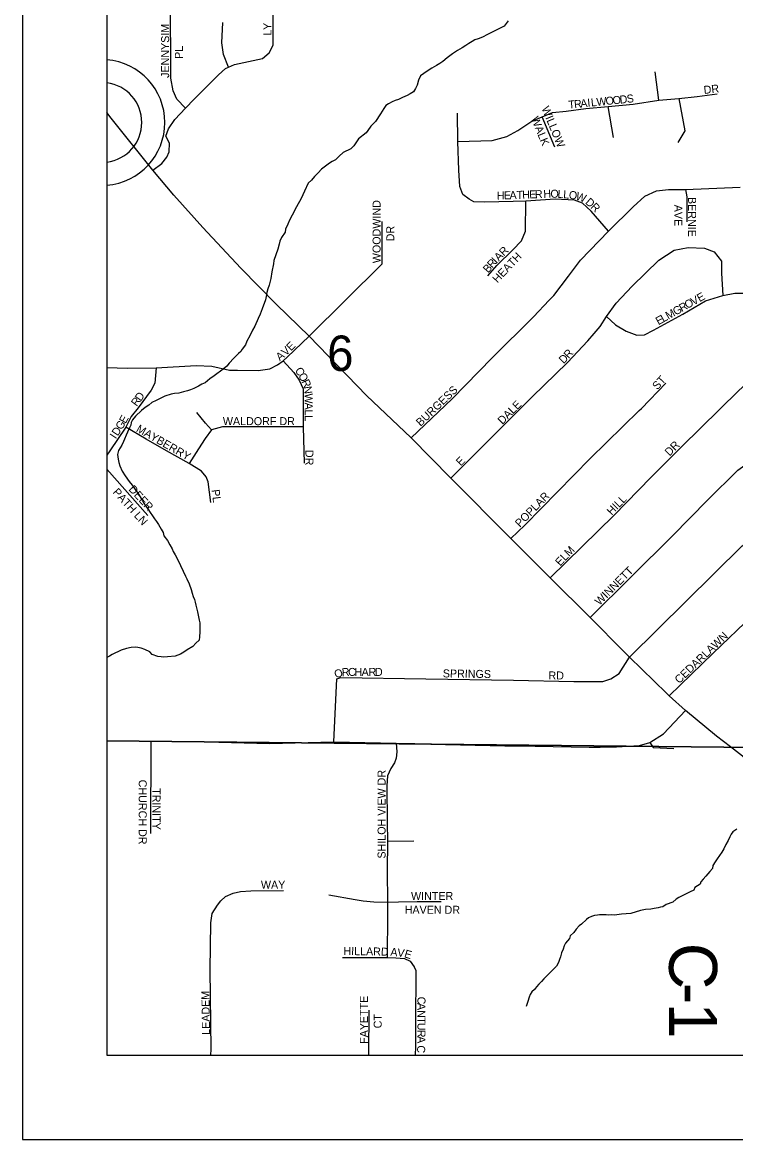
# Model space of a CAD drawing. Extents: x 8.5 to 81.5, y -1.2 to 22.4.
# Drawn here: x 49.353 to 50.196, y 14.351 to 15.672 of the extents above; entities that cross this region are included whole.
import ezdxf

# ---------------------------------------------------------------- set-up
doc = ezdxf.new("R2010")
doc.units = 0
for name, color, linetype in [('GM_X_County', 7, 'Continuous'), ('GM_X_County_Road', 7, 'Continuous'), ('GM_X_County_Road_Text', 7, 'Continuous'), ('GM_X_Minor_River', 7, 'Continuous'), ('GM_X_Section', 7, 'Continuous'), ('GM_X_Section_Text', 7, 'Continuous'), ('GM_X_State_Route', 7, 'Continuous'), ('GM_X_Township', 7, 'Continuous'), ('GM_X_Township_Road', 7, 'Continuous'), ('GM_X_Township_Subdivision', 7, 'Continuous'), ('GM_X_Township_Subdivision_Text', 7, 'Continuous'), ('GM_X_Unincorporated', 7, 'Continuous'), ('SH_Data', 7, 'Continuous')]:
    doc.layers.add(name, color=color, linetype=linetype)

msp = doc.modelspace()

# ---------------------------------------------------------------- linework, layer by layer
at = {"layer": 'GM_X_County'}
msp.add_lwpolyline([(54.0879, 21.2506), (49.4527, 21.2506), (49.4527, 14.4506), (56.2527, 14.4506), (56.2527, 19.1108)], dxfattribs=at)
at = {"layer": 'GM_X_County_Road'}
msp.add_lwpolyline([(49.4527, 14.8224), (49.5047, 14.8219), (49.5551, 14.8213), (49.6451, 14.819), (49.721, 14.821), (49.7946, 14.8196), (49.8168, 14.8191), (49.8359, 14.8182), (49.9231, 14.8164), (49.9377, 14.8162), (50.0228, 14.8149), (50.0359, 14.8149), (50.0554, 14.8152), (50.0823, 14.8169), (50.0945, 14.8203), (50.1107, 14.8305), (50.1369, 14.8581)], dxfattribs=at)
at = {"layer": 'GM_X_Minor_River'}
for points in [[(49.927, 15.6737), (49.9223, 15.6677), (49.9139, 15.6633), (49.9089, 15.6607), (49.9027, 15.6578), (49.8966, 15.6545), (49.8916, 15.6527), (49.8878, 15.6513), (49.8844, 15.6494), (49.8805, 15.6472), (49.877, 15.6446), (49.8728, 15.642), (49.8674, 15.6387), (49.8613, 15.6347), (49.8551, 15.6302), (49.8497, 15.6258), (49.8462, 15.6232), (49.8424, 15.621), (49.837, 15.6177), (49.8324, 15.6151), (49.8274, 15.6114), (49.8236, 15.6088), (49.8212, 15.6035), (49.8195, 15.5979), (49.8176, 15.5937), (49.8152, 15.59), (49.8114, 15.5874), (49.8079, 15.5855), (49.8022, 15.583), (49.7976, 15.5808), (49.7934, 15.5794), (49.7899, 15.5779), (49.7857, 15.5757), (49.7826, 15.5735), (49.7803, 15.5701), (49.776, 15.5638), (49.7701, 15.5547), (49.7647, 15.5491), (49.7611, 15.5443), (49.7592, 15.5413), (49.7503, 15.5342), (49.7448, 15.526), (49.741, 15.5226), (49.7321, 15.5179), (49.7275, 15.5138), (49.7229, 15.5093), (49.719, 15.5075)], [(49.719, 15.5075), (49.716, 15.5056), (49.7063, 15.4982), (49.7024, 15.4941), (49.6982, 15.4896), (49.6947, 15.4855), (49.6908, 15.4818), (49.6864, 15.4724), (49.6825, 15.4637), (49.6769, 15.4539), (49.6718, 15.4441), (49.6687, 15.4381), (49.6667, 15.4332), (49.6639, 15.4276), (49.6634, 15.4238), (49.6591, 15.4174), (49.6571, 15.4133), (49.6563, 15.4098), (49.6547, 15.4038), (49.6526, 15.397), (49.6502, 15.3902), (49.6498, 15.3864), (49.6477, 15.3769), (49.6464, 15.369), (49.6447, 15.361), (49.6431, 15.3569), (49.6418, 15.3527), (49.641, 15.3478), (49.6401, 15.344), (49.6361, 15.333), (49.6341, 15.327), (49.6317, 15.3217), (49.6277, 15.3127), (49.625, 15.3078), (49.6218, 15.3014), (49.6183, 15.295), (49.6167, 15.2908), (49.6128, 15.2856), (49.6112, 15.2826), (49.6081, 15.2804), (49.6027, 15.2748), (49.5972, 15.2688), (49.5945, 15.2654), (49.5903, 15.2617), (49.5795, 15.2539), (49.5745, 15.2502), (49.5687, 15.2458), (49.5649, 15.2439), (49.561, 15.2417), (49.5553, 15.2388), (49.5514, 15.2374), (49.548, 15.2363), (49.5434, 15.2349), (49.5377, 15.2335), (49.5328, 15.2332), (49.5286, 15.2321), (49.5213, 15.23), (49.5179, 15.2285), (49.5148, 15.2267), (49.511, 15.2249), (49.506, 15.2223), (49.5021, 15.2193), (49.4979, 15.2164), (49.4936, 15.213), (49.4867, 15.2063), (49.4828, 15.2018), (49.4812, 15.1988), (49.4808, 15.1954), (49.4795, 15.1924), (49.4772, 15.1875), (49.4756, 15.1837), (49.4736, 15.1792), (49.4724, 15.1762), (49.4704, 15.172), (49.4684, 15.1686), (49.4665, 15.1656), (49.4652, 15.1611), (49.4659, 15.1554), (49.4669, 15.1516), (49.468, 15.1474), (49.4709, 15.1412), (49.4742, 15.1358), (49.479, 15.1289), (49.4827, 15.1246), (49.486, 15.1196), (49.4893, 15.115), (49.4919, 15.1107), (49.4945, 15.1069), (49.4963, 15.1034), (49.4985, 15.1003), (49.5011, 15.0965), (49.5037, 15.0922), (49.5066, 15.0884), (49.5088, 15.0849), (49.5114, 15.0818), (49.5136, 15.078), (49.5169, 15.0726), (49.5191, 15.0687), (49.5202, 15.0649), (49.5242, 15.0591), (49.5272, 15.0541)], [(49.5272, 15.0541), (49.5297, 15.0495), (49.5312, 15.046), (49.5334, 15.0422), (49.537, 15.0356), (49.5457, 15.0172), (49.5472, 15.0138), (49.5501, 15.008), (49.5522, 15.0011), (49.5537, 14.9969), (49.5547, 14.9931), (49.5562, 14.9896), (49.5569, 14.9862), (49.5579, 14.9827), (49.559, 14.9778), (49.5597, 14.9747), (49.5611, 14.969), (49.5617, 14.9651), (49.5624, 14.9617), (49.5626, 14.951), (49.5621, 14.9453), (49.5616, 14.9415), (49.5578, 14.9378), (49.5543, 14.9337), (49.5474, 14.9297), (49.5435, 14.9271), (49.5397, 14.9249), (49.5366, 14.9234), (49.5335, 14.9223), (49.5244, 14.9217), (49.5202, 14.9214), (49.5168, 14.9215), (49.513, 14.922), (49.5063, 14.9244), (49.5033, 14.9275), (49.4977, 14.9303), (49.4931, 14.9319), (49.4894, 14.9327), (49.486, 14.9332), (49.4814, 14.9325), (49.4757, 14.9315), (49.4696, 14.9293), (49.4588, 14.9242), (49.4558, 14.9223), (49.4527, 14.9209)], [(50.1975, 14.7176), (50.1929, 14.7147), (50.1909, 14.7117), (50.1893, 14.7086), (50.1874, 14.7045), (50.1846, 14.6996), (50.1822, 14.6947), (50.1799, 14.6906), (50.1744, 14.6827), (50.172, 14.6793), (50.1693, 14.6748), (50.1688, 14.6714), (50.1657, 14.6676), (50.1607, 14.662), (50.1579, 14.6586), (50.1548, 14.6553), (50.154, 14.6526), (50.1479, 14.6486), (50.1467, 14.6455), (50.1425, 14.6437), (50.1382, 14.6415), (50.1329, 14.639), (50.129, 14.6368), (50.1256, 14.6349), (50.1217, 14.6316), (50.1141, 14.6287), (50.1102, 14.6261), (50.1072, 14.6254), (50.1045, 14.6247), (50.0996, 14.624), (50.0957, 14.6233), (50.0897, 14.6227), (50.0836, 14.6217), (50.0721, 14.6181), (50.0611, 14.6172), (50.0558, 14.6165), (50.0523, 14.6162), (50.0489, 14.6163), (50.0463, 14.616), (50.0429, 14.6164)], [(50.0429, 14.6164), (50.0353, 14.6166), (50.0326, 14.6162), (50.0292, 14.6155), (50.0257, 14.6145), (50.0223, 14.613), (50.0196, 14.6108), (50.0138, 14.6056), (50.0111, 14.6033), (50.0076, 14.5996), (50.0049, 14.5955), (50.0006, 14.5917), (49.9998, 14.5883), (49.9951, 14.5831), (49.9935, 14.5797), (49.9923, 14.5759), (49.9903, 14.5714), (49.9891, 14.5668), (49.9879, 14.5638), (49.9867, 14.56), (49.9843, 14.5559), (49.9781, 14.5495), (49.9715, 14.5432), (49.9692, 14.5406), (49.9665, 14.5376), (49.9634, 14.5346), (49.9606, 14.5312), (49.9583, 14.5282), (49.9552, 14.5253), (49.9533, 14.5222), (49.9521, 14.5192), (49.9504, 14.5139), (49.9492, 14.5105), (49.9484, 14.5079)]]:
    msp.add_lwpolyline(points, dxfattribs=at)
at = {"layer": 'GM_X_Section'}
msp.add_line((49.4527, 15.7683), (49.4527, 14.8223), dxfattribs=at)
for points in [[(49.4527, 14.8223), (50.2203, 14.8143), (50.2298, 15.7659), (49.4527, 15.7683)], [(49.4527, 14.8223), (49.4527, 14.4506), (50.2199, 14.4506)], [(50.2199, 14.4506), (50.219, 14.7462), (50.2203, 14.8143), (49.4527, 14.8223)]]:
    msp.add_lwpolyline(points, dxfattribs=at)
at = {"layer": 'GM_X_State_Route'}
for points in [[(49.9326, 15.059), (49.9303, 15.0614), (49.8595, 15.1329), (49.8123, 15.1806), (49.7598, 15.2308), (49.6917, 15.301), (49.6534, 15.3385), (49.611, 15.3814), (49.5661, 15.4295), (49.5317, 15.4678), (49.507, 15.497), (49.4579, 15.5586), (49.4527, 15.5653)], [(50.0641, 14.928), (50.0242, 14.968), (49.9768, 15.0149), (49.9326, 15.059)], [(50.1144, 14.8787), (50.0707, 14.9213), (50.0641, 14.928)], [(50.1899, 14.8152), (50.1734, 14.8279), (50.1369, 14.8581), (50.1177, 14.8754), (50.1144, 14.8787)], [(50.5585, 14.4506), (50.5576, 14.4519), (50.5438, 14.4699), (50.524, 14.4914), (50.4321, 14.5898), (50.4041, 14.6199), (50.3659, 14.6612), (50.3179, 14.7117), (50.2995, 14.7293), (50.2169, 14.7944), (50.1899, 14.8152)]]:
    msp.add_lwpolyline(points, dxfattribs=at)
at = {"layer": 'GM_X_Township'}
msp.add_lwpolyline([(49.4527, 15.7601), (49.4527, 14.4506), (54.4602, 14.4506)], dxfattribs=at)
at = {"layer": 'GM_X_Township_Road'}
msp.add_lwpolyline([(50.0945, 14.8203), (50.0984, 14.8145), (50.1231, 14.8133)], dxfattribs=at)
at = {"layer": 'GM_X_Township_Subdivision'}
for points in [[(49.5458, 15.5704), (49.5355, 15.581), (49.5309, 15.5909), (49.5282, 15.6062), (49.5282, 15.6412), (49.5276, 15.6942), (49.5289, 15.7081), (49.5329, 15.7193)], [(49.507, 15.497), (49.5177, 15.5052), (49.5234, 15.5124), (49.5262, 15.5189), (49.5268, 15.5293), (49.5223, 15.5373), (49.5256, 15.5459), (49.5329, 15.5572), (49.5458, 15.5704), (49.556, 15.581), (49.5845, 15.6101), (49.5931, 15.6174), (49.5965, 15.6189), (49.6037, 15.622), (49.6368, 15.6293), (49.6447, 15.6359), (49.6493, 15.6452), (49.6493, 15.6677), (49.6487, 15.7034)], [(49.5965, 15.6189), (49.5905, 15.6339), (49.5885, 15.6479), (49.5898, 15.6717)], [(50.1052, 15.5801), (50.1011, 15.6134)], [(49.8678, 15.5312), (49.9083, 15.5323), (49.9257, 15.5372), (49.9386, 15.5442), (49.9553, 15.5553), (49.9675, 15.5601), (49.9797, 15.5653), (49.9956, 15.5668), (50.019, 15.5701), (50.0452, 15.5723), (50.0748, 15.5753), (50.1052, 15.5801), (50.1289, 15.5818), (50.1507, 15.5845), (50.1741, 15.5875)], [(50.1289, 15.5818), (50.1362, 15.5437), (50.1279, 15.5299)], [(50.0515, 15.536), (50.0452, 15.5723)], [(50.0458, 15.425), (50.0252, 15.4487), (50.0152, 15.4583), (50.0056, 15.4616), (49.9827, 15.4627), (49.9482, 15.4605), (49.9331, 15.4602), (49.899, 15.4594), (49.8864, 15.4598), (49.8809, 15.4627), (49.8734, 15.4686), (49.8698, 15.4777), (49.8689, 15.497), (49.8678, 15.5312), (49.8672, 15.5646)], [(49.9824, 15.5244), (49.9675, 15.5601)], [(49.9756, 15.3433), (49.9812, 15.3491), (49.9986, 15.372), (50.0127, 15.3909), (50.0458, 15.425), (50.0748, 15.4539), (50.0889, 15.4664), (50.1026, 15.4727), (50.1167, 15.4742), (50.137, 15.4742), (50.2015, 15.4772)], [(50.137, 15.4742), (50.1382, 15.4657), (50.1385, 15.4361)], [(49.9031, 15.3724), (49.9138, 15.3846), (49.9327, 15.4031), (49.9431, 15.4135), (49.9475, 15.425), (49.9482, 15.4605)], [(49.7782, 15.3865), (49.7782, 15.4365)], [(50.0287, 15.304), (50.0358, 15.3122), (50.0433, 15.3241), (50.0549, 15.3399), (50.0738, 15.36), (50.1052, 15.3908), (50.1236, 15.4025), (50.14, 15.4058), (50.1594, 15.405), (50.1708, 15.4005), (50.1795, 15.3896), (50.1794, 15.3755), (50.1808, 15.3491)], [(49.6917, 15.301), (49.7782, 15.3865)], [(49.8123, 15.1806), (49.8611, 15.2268), (49.9083, 15.2753), (49.9571, 15.3239), (49.9756, 15.3433)], [(50.0433, 15.3241), (50.0541, 15.3144), (50.0666, 15.3066), (50.0791, 15.3022), (50.0883, 15.3024), (50.0988, 15.308), (50.1336, 15.3269), (50.1605, 15.3427), (50.1808, 15.3491), (50.195, 15.3516), (50.2089, 15.3519), (50.2228, 15.3516), (50.2425, 15.3505), (50.2623, 15.3494), (50.2767, 15.341), (50.2851, 15.334), (50.2901, 15.3241), (50.2906, 15.3122), (50.2898, 15.2876)], [(49.8595, 15.1329), (49.9113, 15.185), (49.9556, 15.2291), (49.9974, 15.2696), (50.0213, 15.2955), (50.0287, 15.304)], [(49.6072, 15.2606), (49.6317, 15.2603), (49.6453, 15.2622), (49.6544, 15.2668), (49.6611, 15.2718), (49.6659, 15.2759), (49.6917, 15.301)], [(49.9768, 15.0149), (50.0523, 15.089), (50.0959, 15.1337), (50.1326, 15.1704), (50.1995, 15.2363), (50.2138, 15.2494), (50.2374, 15.2728), (50.2475, 15.2815), (50.2564, 15.2867), (50.2898, 15.2876), (50.3267, 15.286), (50.3534, 15.2866), (50.3868, 15.2844), (50.416, 15.2821), (50.4751, 15.2804)], [(49.4527, 15.2637), (49.477, 15.2632), (49.511, 15.2635), (49.5581, 15.2663), (49.5768, 15.2654), (49.5975, 15.2607), (49.6072, 15.2606)], [(49.511, 15.2635), (49.5093, 15.2453), (49.5052, 15.2371), (49.4895, 15.2161), (49.4813, 15.2057), (49.475, 15.1934), (49.4562, 15.1653), (49.4527, 15.1601)], [(49.6611, 15.2718), (49.6736, 15.258), (49.6802, 15.2487), (49.6849, 15.2384), (49.6848, 15.1938), (49.686, 15.1506)], [(50.0847, 15.2154), (50.1137, 15.2452)], [(49.5763, 15.19), (49.5692, 15.198), (49.5591, 15.2104)], [(49.9303, 15.0614), (49.9469, 15.0773), (50.0242, 15.156), (50.0822, 15.2128), (50.0847, 15.2154)], [(49.5754, 15.104), (49.5723, 15.1286), (49.5699, 15.1346), (49.5645, 15.1412), (49.55, 15.1501), (49.5233, 15.1652), (49.4993, 15.1792), (49.475, 15.1934)], [(49.6848, 15.1938), (49.6184, 15.1935), (49.5977, 15.1938), (49.5894, 15.1937), (49.5763, 15.19), (49.5689, 15.1799), (49.5609, 15.1678), (49.55, 15.1501)], [(50.0242, 14.968), (50.1215, 15.0647), (50.1629, 15.1069), (50.1986, 15.1425), (50.2163, 15.1551), (50.2296, 15.156), (50.3005, 15.1544), (50.3402, 15.1542), (50.36, 15.1544)], [(49.5012, 15.0889), (49.4527, 15.1436)], [(49.721, 14.821), (49.7244, 14.8955), (49.7293, 14.8972), (49.8298, 14.8955), (49.9335, 14.8939), (50.0049, 14.8923), (50.0389, 14.8923), (50.0487, 14.8955), (50.0584, 14.902), (50.0707, 14.9213), (50.2038, 15.053), (50.2157, 15.0601), (50.3461, 15.0636), (50.3952, 15.0691)], [(50.1177, 14.8754), (50.1694, 14.9259), (50.2164, 14.9709), (50.2436, 14.9728), (50.2814, 14.9717), (50.2912, 14.9655), (50.3251, 14.9423)], [(49.5047, 14.8219), (49.5044, 14.7128)], [(49.7946, 14.8196), (49.7954, 14.8091), (49.7947, 14.8017), (49.7929, 14.7962), (49.7883, 14.7897), (49.7843, 14.7809), (49.7835, 14.7692), (49.784, 14.7256), (49.7845, 14.7034), (49.7839, 14.6685), (49.7843, 14.6316), (49.7843, 14.6174), (49.7842, 14.5658)], [(49.7845, 14.7034), (49.8156, 14.7038)], [(49.5756, 14.4506), (49.5761, 14.4574), (49.5749, 14.5514), (49.5755, 14.6069), (49.5772, 14.6182), (49.5834, 14.6278), (49.5874, 14.6329), (49.593, 14.638), (49.6021, 14.642), (49.6106, 14.6442), (49.623, 14.6448), (49.6615, 14.6454)], [(49.7152, 14.6403), (49.7461, 14.6347), (49.7555, 14.6329), (49.7683, 14.6318), (49.7843, 14.6316), (49.7974, 14.632), (49.8197, 14.6322), (49.8479, 14.6322)], [(49.7312, 14.566), (49.7842, 14.5658), (49.7945, 14.5655), (49.8045, 14.5649), (49.8112, 14.5616), (49.8159, 14.5551)], [(49.8176, 14.4506), (49.8176, 14.4506), (49.8179, 14.4608), (49.818, 14.5014), (49.8184, 14.537), (49.8182, 14.5506), (49.8159, 14.5551)], [(49.7623, 14.4506), (49.7627, 14.5038)]]:
    msp.add_lwpolyline(points, dxfattribs=at)
at = {"layer": 'GM_X_Unincorporated'}
for p, q in [((49.4527, 15.6277), (49.4527, 15.4794)), ((49.4527, 15.6004), (49.4527, 15.5068))]:
    msp.add_line(p, q, dxfattribs=at)
for radius, start, end in [(0.0744, 274.5475, 85.4525), (0.0472, 277.1851, 82.8149)]:
    msp.add_arc((49.4468, 15.5536), radius, start, end, dxfattribs=at)
at = {"layer": 'SH_Data'}
for p, q in [((49.3527, 21.3506), (49.3527, 14.3506)), ((49.4527, 21.2506), (49.4527, 14.4506)), ((49.4527, 14.4506), (56.2527, 14.4506)), ((49.3527, 14.3506), (56.3527, 14.3506))]:
    msp.add_line(p, q, dxfattribs=at)

# ---------------------------------------------------------------- texts
at = {"layer": 'GM_X_County_Road_Text'}
for s, rotation, p in [('C', 269.2233, (50.1178, 14.5837)), ('-', 270.0691, (50.1172, 14.5361)), ('1', 270.2322, (50.1172, 14.5126))]:
    msp.add_text(s, height=0.0568, rotation=rotation, dxfattribs=at).set_placement(p)
at = {"layer": 'GM_X_Section_Text'}
msp.add_text('6', height=0.0419, rotation=0, dxfattribs=at).set_placement((49.7131, 15.2597))
at = {"layer": 'GM_X_Township_Subdivision_Text'}
for s, rotation, p in [('JENNYSIM', 90, (49.5263, 15.6063)), ('Y', 89.9344, (49.6472, 15.663)), ('L', 89.9453, (49.6472, 15.6563)), ('PL', 90, (49.5425, 15.6288)), ('DR', 6.3375, (50.1588, 15.5873)), ('R', 5.7087, (50.0055, 15.5704)), ('A', 5.6932, (50.0129, 15.5712)), ('I', 5.691, (50.0212, 15.572)), ('L', 5.7079, (50.0254, 15.5724)), ('W', 5.6922, (50.032, 15.5731)), ('O', 5.7091, (50.0428, 15.5742)), ('O', 5.6932, (50.0511, 15.575)), ('D', 5.7091, (50.0594, 15.5758)), ('S', 6.5344, (50.0678, 15.5767)), ('WILLOW', 292.5419, (49.9664, 15.5704)), ('T', 5.6916, (49.9988, 15.5698)), ('WALK', 292.304, (49.9539, 15.5583)), ('H', 2.0766, (49.9139, 15.4623)), ('E', 2.0766, (49.9222, 15.4626)), ('A', 2.0766, (49.9289, 15.4628)), ('T', 2.0493, (49.9372, 15.4631)), ('H', 2.0886, (49.9439, 15.4634)), ('E', 2.0903, (49.9522, 15.4637)), ('R', 2.0838, (49.9589, 15.4639)), ('H', 2.0781, (49.9689, 15.4643)), ('O', 359.7377, (49.9771, 15.4646)), ('L', 356.0623, (49.9853, 15.4645)), ('L', 354.9664, (49.9919, 15.4641)), ('O', 353.6936, (49.9985, 15.4635)), ('W', 340.7568, (50.0062, 15.4627)), ('D', 319.3466, (50.0176, 15.4582)), ('BERNIE', 270, (50.1399, 15.4655)), ('WOODWIND', 90, (49.7763, 15.3872)), ('R', 316.46, (50.0239, 15.4528)), ('AVE', 270, (50.1236, 15.4563)), ('DR', 90, (49.7925, 15.413)), ('HEATH', 46.7381, (49.9145, 15.3631)), ('A', 45.3399, (49.9161, 15.3891)), ('R', 45, (49.922, 15.395)), ('B', 49.3144, (49.9035, 15.3749)), ('R', 48.9877, (49.9084, 15.3806)), ('I', 45.773, (49.9132, 15.3861)), ('O', 29.2731, (50.1389, 15.3329)), ('V', 29.2542, (50.1462, 15.3369)), ('E', 29.1687, (50.1535, 15.341)), ('M', 29.2704, (50.1164, 15.3202)), ('G', 29.2542, (50.1251, 15.3251)), ('R', 29.2629, (50.1324, 15.3292)), ('E', 29.2536, (50.1048, 15.3137)), ('L', 29.2804, (50.1106, 15.317)), ('V', 43.5978, (49.6642, 15.2769)), ('E', 45.0126, (49.6704, 15.2828)), ('A', 38.8203, (49.6571, 15.2711)), ('D', 46.3753, (49.9928, 15.2676)), ('R', 47.5881, (49.9987, 15.2737)), ('C', 301.197, (49.6746, 15.2606)), ('O', 299.7828, (49.6785, 15.2543)), ('R', 293.8269, (49.6825, 15.2473)), ('ST', 47.4879, (50.1035, 15.2367)), ('N', 277.8705, (49.6853, 15.2411)), ('BURGESS', 43.723, (49.8236, 15.1935)), ('R', 52.7853, (49.4879, 15.217)), ('D', 53.7066, (49.4926, 15.2231)), ('W', 270.5716, (49.6865, 15.2331)), ('DALE', 45, (49.9203, 15.1958)), ('A', 270, (49.6866, 15.2223)), ('L', 269.9956, (49.6866, 15.214)), ('G', 58.4734, (49.4702, 15.1893)), ('E', 61.2031, (49.4748, 15.1968)), ('WALDORF DR', 0, (49.5898, 15.1956)), ('L', 269.9956, (49.6866, 15.2073)), ('I', 56.8313, (49.4632, 15.1786)), ('D', 56.8746, (49.4655, 15.1821)), ('MAYBERRY', 330.2541, (49.4865, 15.1886)), ('DR', 45, (50.1178, 15.1584)), ('DR', 270, (49.6874, 15.1663)), ('E', 45, (49.8711, 15.1467)), ('PATH LN', 312.2061, (49.459, 15.1158)), ('DEER', 312.7063, (49.4777, 15.1192)), ('PL', 277.1217, (49.5764, 15.119)), ('POPLAR', 45.7606, (49.941, 15.0742)), ('HILL', 45.9405, (50.0495, 15.0884)), ('ELM', 46.4019, (49.9886, 15.0283)), ('WINNETT', 45, (50.0352, 14.9818)), ('CEDARLAWN', 43.648, (50.1294, 14.8893)), ('O', 19.1261, (49.7234, 14.896)), ('R', 2.9158, (49.7306, 14.8986)), ('C', 0, (49.7379, 14.899)), ('H', 0, (49.7454, 14.899)), ('A', 0, (49.7538, 14.899)), ('R', 0, (49.7621, 14.899)), ('D', 0, (49.7696, 14.899)), ('SPRINGS', 359.1454, (49.8498, 14.8973)), ('RD', 0, (49.9748, 14.8948)), ('CHURCH DR', 270, (49.4903, 14.7763)), ('SHILOH VIEW DR', 90, (49.7822, 14.683)), ('TRINITY', 270, (49.5066, 14.7663)), ('WAY', 0, (49.6348, 14.6473)), ('WINTER', 0, (49.8123, 14.634)), ('HAVEN DR', 0, (49.8048, 14.6177)), ('HILLARD', 359.0578, (49.7323, 14.569)), ('A', 354.3525, (49.7875, 14.5681)), ('V', 353.2519, (49.7957, 14.5673)), ('E', 343.6043, (49.8036, 14.5664)), ('LEADEM', 90.9873, (49.5747, 14.4746)), ('FAYETTE', 90, (49.7613, 14.4638)), ('C', 269.9271, (49.8199, 14.5197)), ('A', 269.9253, (49.8199, 14.5122)), ('CT', 90, (49.7776, 14.4822)), ('N', 269.9253, (49.8199, 14.5038)), ('U', 269.9253, (49.8199, 14.4888)), ('T', 269.918, (49.8199, 14.4955)), ('R', 269.9228, (49.8199, 14.4805)), ('A', 269.9253, (49.8199, 14.473)), ('C', 266.8417, (49.8198, 14.4623))]:
    msp.add_text(s, height=0.00947, rotation=rotation, dxfattribs=at).set_placement(p)

doc.saveas('drawing.dxf')
